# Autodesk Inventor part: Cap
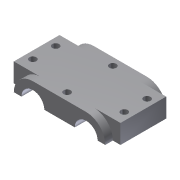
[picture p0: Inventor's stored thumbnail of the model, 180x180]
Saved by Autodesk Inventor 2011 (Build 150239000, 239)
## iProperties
Shininess: 77.0
Length Units: 11269
Angle Units: 11279
Time Units: 11290
Mass Units: 11283
Length Display Precision: 3
Angle Display Precision: 2
Created: 2002-02
Part Number: Cap
Document SubType Name: Modeling
Designer: ***
Density: 1 g/cm^3
Density: 0.0
Volumn: 0.0
Area: 0.0
PropertySet Name: Model Information
Control State: 0
Master: False
Checked Out: False
Author: ***
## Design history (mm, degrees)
sketch "Sketch2"
  geometry: L1 (-17.5, 12.5)-(17.5, 12.5); L2 (30, 0)-(25, 0); L3 (10, 0)-(-10, 0); L4 (-25, 0)-(-30, 0); A1 r 12.5 centre (-17.5, 0) between (-17.5, 12.5) and (-30, 0); A2 r 12.5 centre (17.5, 0) between (30, 0) and (17.5, 12.5); A3 r 7.5 centre (17.5, 0) between (25, 0) and (10, 0); A4 r 7.5 centre (-17.5, 0) between (-10, 0) and (-25, 0)
  constraints: 8 end point, 8 point on circle, 4 centre point, 3 horizontal, 3 parallel, 2 coincident, 2 equal radius, 2 tangent
  dimensions: "d0" = 12.5 radius of A1; "d1" = 7.5 radius of A4; "d2" = 35 distance of A1.centre A2.centre; "d3" = 12.5 distance between parallel lines of L1 L3
extrude "Extrusion1" new body sketch "Sketch2" stored distance "d4" = 40; taper "d5" = 0 deg
workplane "Work Plane1"
sketch "Sketch3"
  geometry: L1 (-15, 12.5)-(15, 12.5); L2 (15, 12.5)-(15, 0); L3 (15, 0)-(-15, 0); L4 (-15, 0)-(-15, 12.5); L5 (-20, 0)-(20, 0) reference; L6 (-20, 12.5)-(20, 12.5) reference; L7 (20, 12.5)-(20, 0) reference
  constraints: 8 end point, 2 collinear, 2 parallel, 1 horizontal, 1 perpendicular
  dimensions: "d7" = 30 distance of L2.end L3.end; "d8" = 5 distance between parallel lines of L7 L2
extrude "Extrusion2" join sketch "Sketch3" stored distance "d9" = 40; taper "d10" = 0 deg
mirror "Mirror1"
sketch "Sketch4"
  geometry: L1 (-17.5, -35)-(0, -35) reference; L2 (-17.5, -35)-(-17.5, -5) reference; 1 further point
  dimensions: "d12" = 7.5 distance from line of L1 point (-12.5, -27.5); "d13" = 5 distance from line of L2 point (-12.5, -27.5)
hole "Hole1" sketch "Sketch4" at (-12.5, -27.5) diameter "d14" = 4.5; stored, may be unused: countersink angle "d18" = 82 deg, drill point angle "d20" = 118 deg; dims "d15" = 6, "d16" = 4, "d17" = 2, "d19" = 8
pattern_linear "Rectangular Pattern1" dims "d23" = 60, "d26" = 15
sketch "Sketch5"
  geometry: L1 (0, -40)-(35, -40) reference; L2 (-17.5, -35)-(-17.5, -5) reference; 1 further point
  dimensions: "d27" = 5 distance from line of L1 point (17.5, -35); "d28" = 35 distance from line of L2 point (17.5, -35)
hole "Hole2" sketch "Sketch5" at (17.5, -35) diameter "d29" = 4.5; stored, may be unused: countersink angle "d33" = 82 deg, drill point angle "d35" = 118 deg; dims "d30" = 6, "d31" = 4, "d32" = 2, "d34" = 8
pattern_linear "Rectangular Pattern2" dims "d38" = 30
body "Solid1"
other parameters: "d11" = 35
